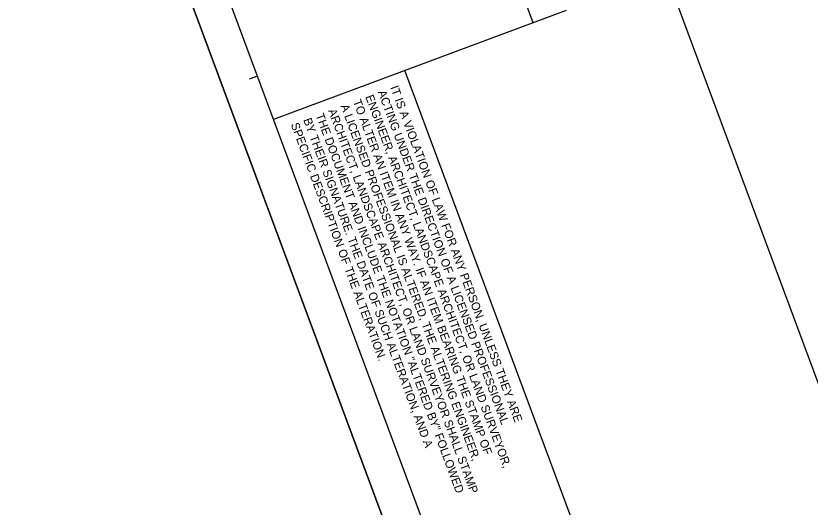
# Model space of a CAD drawing. Extents: x 1040172 to 1040822, y 1127790 to 1128580.
# Drawn here: x 1040172.1 to 1040398.7, y 1128148.3 to 1128288.4 of the extents above; entities that cross this region are included whole.
import ezdxf

# ---------------------------------------------------------------- set-up
doc = ezdxf.new("R2010")
doc.units = 0
for name, color, linetype in [('clip boundary', 7, 'Continuous'), ('SHEET_BORDER', 7, 'Continuous'), ('SHEET_BORDER_CUT', 7, 'Continuous'), ('SHEET_BORDER_STAMPBOX', 7, 'Continuous')]:
    doc.layers.add(name, color=color, linetype=linetype)

msp = doc.modelspace()

# ---------------------------------------------------------------- linework, layer by layer
at = {"layer": 'clip boundary'}
for points in [[(1040584.48, 1128580.33), (1040821.52, 1127942.99), (1040409.12, 1127789.61), (1040172.08, 1128426.95)], [(1040311.42, 1128424.61), (1040504.79, 1127904.67), (1040760.34, 1127999.71), (1040566.96, 1128519.66)]]:
    msp.add_lwpolyline(points, close=True, dxfattribs=at)
at = {"layer": 'SHEET_BORDER'}
msp.add_line((1040241.01, 1128271.21), (1040238.66, 1128270.34), dxfattribs=at)
msp.add_lwpolyline([(1040412.42, 1127817.51), (1040409.2, 1127818.98), (1040191.33, 1128404.77), (1040192.81, 1128407.99), (1040581.19, 1128552.44), (1040584.4, 1128550.96), (1040802.27, 1127965.17), (1040800.8, 1127961.95)], close=True, dxfattribs=at)
at = {"layer": 'SHEET_BORDER_CUT'}
msp.add_lwpolyline([(1040172.08, 1128426.95), (1040409.12, 1127789.61), (1040821.52, 1127942.99), (1040584.48, 1128580.33)], close=True, dxfattribs=at)
at = {"layer": 'SHEET_BORDER_STAMPBOX'}
for p, q in [((1040319.69, 1128286.47), (1040264.57, 1128434.68)), ((1040329.06, 1128289.96), (1040245.58, 1128258.91)), ((1040330.5, 1128145.33), (1040283.07, 1128272.85))]:
    msp.add_line(p, q, dxfattribs=at)

# ---------------------------------------------------------------- texts
for s, p in [('IT IS A VIOLATION OF LAW FOR ANY PERSON, UNLESS THEY ARE ', (1040278.85, 1128268.02)), ('TO ALTER AN ITEM IN ANY WAY. IF AN ITEM BEARING THE STAMP OF ', (1040268.22, 1128264.06)), ('ENGINEER, ARCHITECT, LANDSCAPE ARCHITECT, OR LAND SURVEYOR, ', (1040271.77, 1128265.38)), ('ACTING UNDER THE DIRECTION OF A LICENSED PROFESSIONAL ', (1040275.31, 1128266.7)), ('A LICENSED PROFESSIONAL IS ALTERED, THE ALTERING ENGINEER, ', (1040264.68, 1128262.75)), ('THE DOCUMENT AND INCLUDE THE NOTATION "ALTERED BY" FOLLOWED ', (1040257.59, 1128260.11)), ('ARCHITECT, LANDSCAPE ARCHITECT, OR LAND SURVEYOR SHALL STAMP ', (1040261.13, 1128261.43)), ('BY THEIR SIGNATURE. THE DATE OF SUCH ALTERATION, AND A ', (1040254.05, 1128258.79)), ('SPECIFIC DESCRIPTION OF THE ALTERATION.', (1040250.5, 1128257.47))]:
    msp.add_text(s, height=2.4, rotation=290.4011, dxfattribs=at).set_placement(p)

doc.saveas('drawing.dxf')
